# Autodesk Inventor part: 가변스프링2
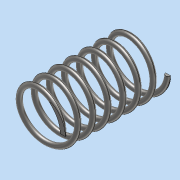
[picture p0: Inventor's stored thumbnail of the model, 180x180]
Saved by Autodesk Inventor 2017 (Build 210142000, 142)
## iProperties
Part Number: 가변스프링2
Material: 스테인레스 스틸
Document SubType Name: Modeling
Designer: MRC
Density: 8 g/cm^3
Appearance: 반연마
Mass: 10.9393 g
Surface Area: 27.6351 cm^2
Volume: 1.36741 cm^3
Author: MRC
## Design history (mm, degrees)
sketch "스케치1"
  geometry: L1 (0, 0)-(10, 0); L2 (10, 0)-(10, 41.411); L3 (10, 41.411)-(0, 41.411); L4 (0, 41.411)-(0, 0); C1 r 1 at (10, 0)
  constraints: 8 end point, 2 parallel, 1 centre point, 1 coincident, 1 horizontal, 1 perpendicular
  dimensions: "d0" = 41.4112 distance of L3.end L1.start (derived); "d1" = 20 diameter of L2 L4; "d2" = 2 diameter of C1
feature "코일1" sketch "스케치1" pitch "d3" = 10; turns "d5" = 7; dims "d4" = 41.4112 (= d0), "d6" = 0, angle "d7" = 90 deg, angle "d8" = 90 deg, "d9" = 0, "d10" = 0
sketch "스케치2"
  geometry: L1 (-20, 41.411)-(20, 41.411); L2 (20, 41.411)-(20, 0); L3 (20, 0)-(-20, 0); L4 (-20, 0)-(-20, 41.411); L5 (0, 41.411)-(0, 0) reference; 2 further points
  constraints: 8 end point, 2 midpoint, 2 parallel, 1 coincident, 1 horizontal, 1 perpendicular
  dimensions: "d11" = 40 distance of L1.start L1.end
extrude "돌출1" sketch "스케치2" stored distance "d12" = 0; taper "d13" = 0 deg
node "솔리드1"
